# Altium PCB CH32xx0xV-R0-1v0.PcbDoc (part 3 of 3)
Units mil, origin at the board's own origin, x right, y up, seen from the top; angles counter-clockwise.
Board outline 3661.42 x 3267.72 mil, 2 copper layers (Top Layer, Bottom Layer); 68 components, 119 nets, 417 pads, 746 vias.
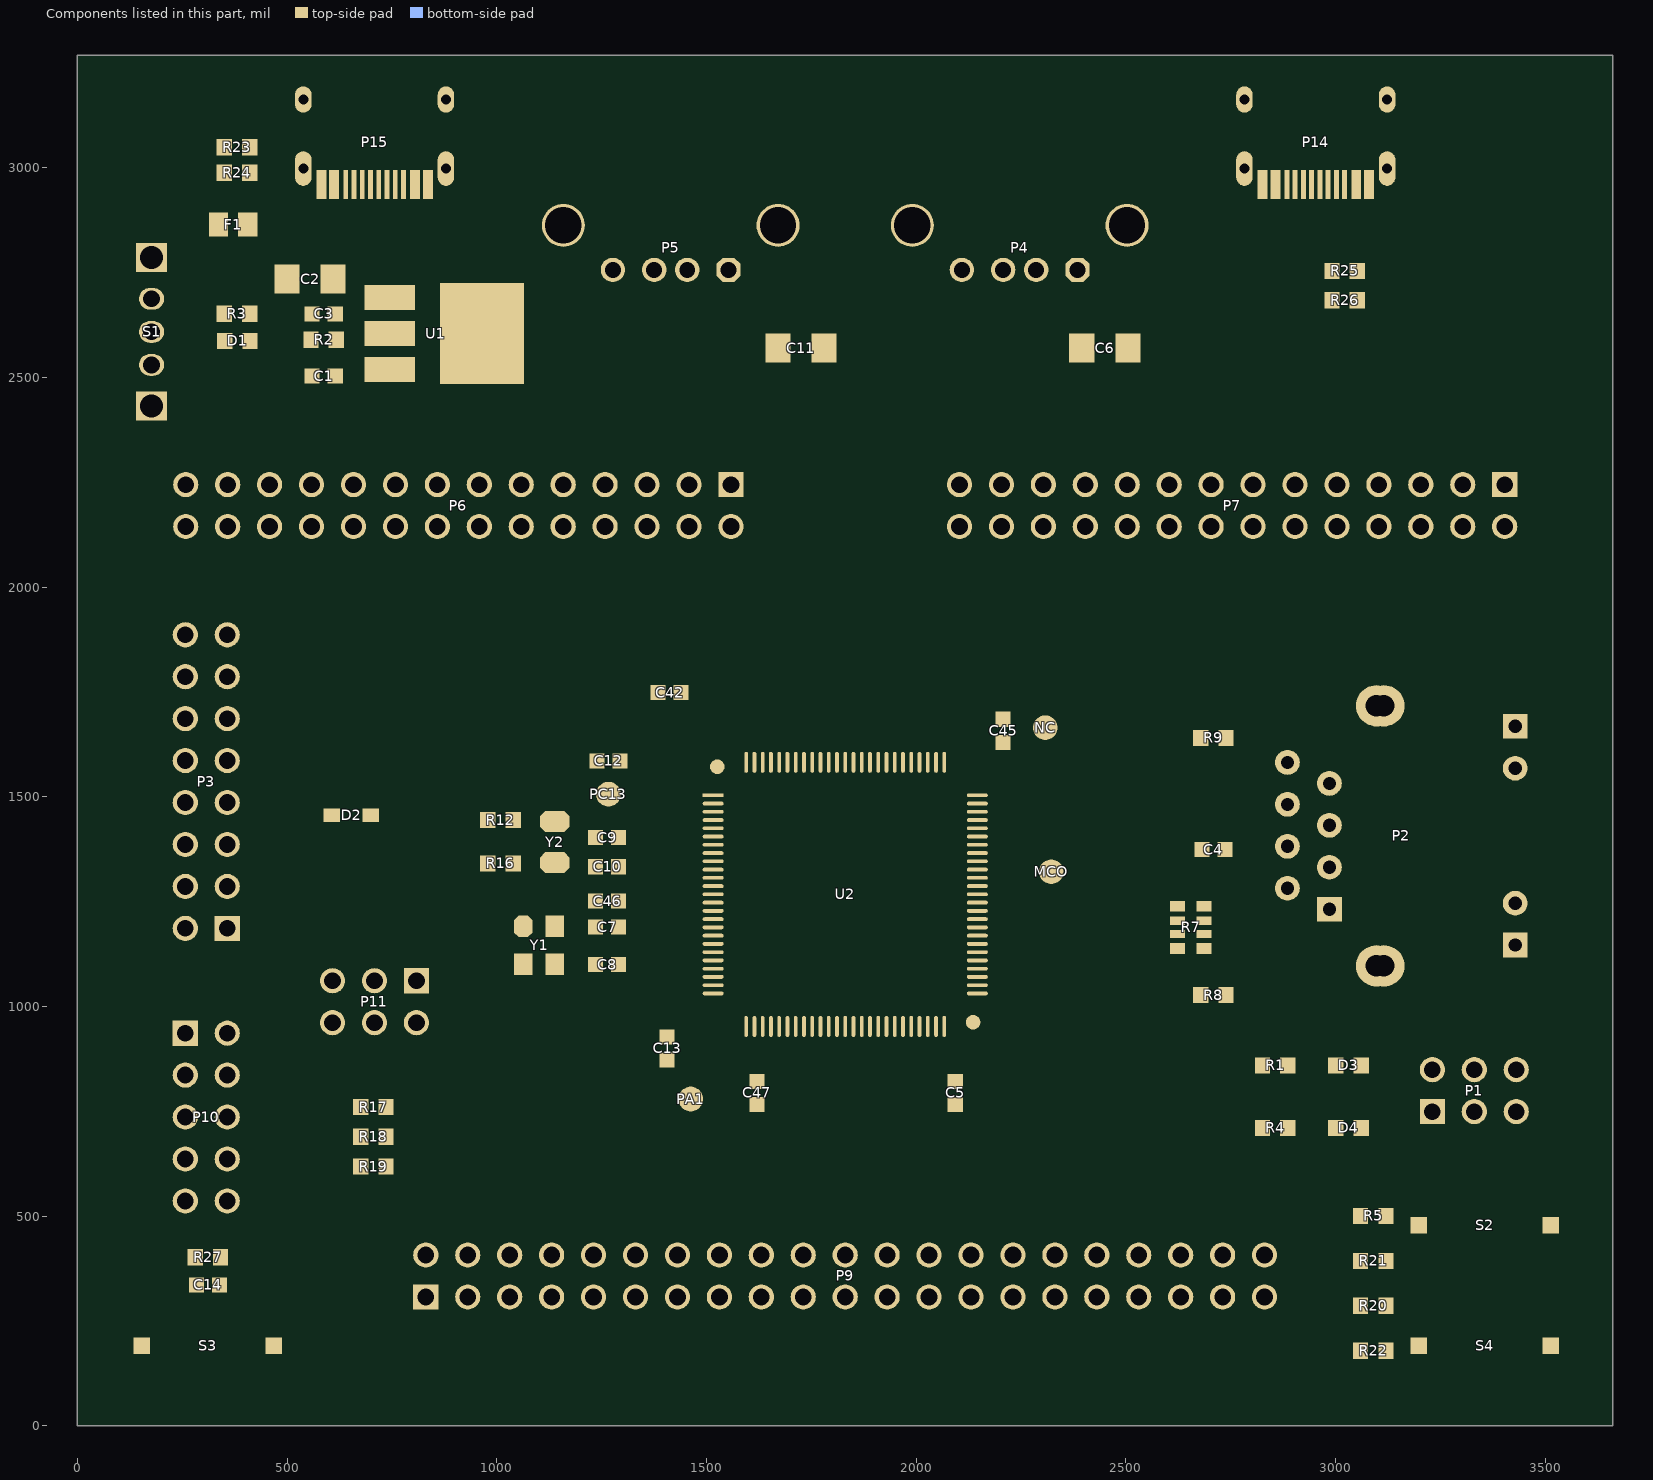
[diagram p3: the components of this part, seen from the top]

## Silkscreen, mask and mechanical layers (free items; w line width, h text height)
Top Overlay:
  lines w10: 471.12,1226.78 471.12,1838.79
  text "OFF" at 24.62,2711.6 h32 r270
  text "ON" at 24.62,2573.76 h32 r270
  text "CH32xx0xV-R0-1v0" at 2720.16,2529.81 h45
  text "PC12" at 2682.57,2465.31 h35 r270
  text "PC10" at 2782.58,2465.31 h35 r270
  text "PA14" at 2882.59,2465.31 h35 r270
  text "PA12" at 2982.6,2465.31 h35 r270
  text "PA10" at 3082.61,2465.31 h35 r270
  text "PC15" at 731.68,2438.82 h35 r270
  text "PC13" at 831.81,2438.82 h35 r270
  text "PB6" at 2082.53,2436.15 h35 r270
  text "PB4" at 2182.54,2436.15 h35 r270
  text "PD7" at 2282.54,2436.15 h35 r270
  text "PD5" at 2382.55,2436.15 h35 r270
  text "PD3" at 2482.56,2436.15 h35 r270
  text "PA8" at 3182.61,2436.15 h35 r270
  text "PC8" at 3282.62,2436.15 h35 r270
  text "PC6" at 3382.63,2436.15 h35 r270
  text "PD1" at 2582.57,2424.49 h35 r270
  text "GND" at 230.13,2409.67 h35 r270
  text "GND" at 330.27,2409.67 h35 r270
  text "PC3" at 531.4,2409.67 h35 r270
  text "PE5" at 931.95,2409.67 h35 r270
  text "PE3" at 1032.09,2409.67 h35 r270
  text "PB9" at 1232.36,2409.67 h35 r270
  text "GND" at 1331.27,2409.67 h35 r270
  text "VIO" at 1431.96,2403.83 h35 r270
  text "VIO" at 1536.38,2403.83 h35 r270
  text "PA1" at 434.68,2398 h35 r270
  text "PC1" at 631.54,2398 h35 r270
  text "PE1" at 1132.22,2398 h35 r270
  text "GND" at 238.88,2082.05 h35 r270
  text "GND" at 339.18,2082.05 h35 r270
  text "PA0" at 435.6,2082.05 h35 r270
  text "PC2" at 540.47,2082.05 h35 r270
  text "PC0" at 640.76,2082.05 h35 r270
  text "PC14" at 741.06,2082.05 h35 r270
  text "PE6" at 841.35,2082.05 h35 r270
  text "PE4" at 941.65,2082.05 h35 r270
  text "PE2" at 1041.94,2082.05 h35 r270
  text "PE0" at 1142.23,2082.05 h35 r270
  text "PB8" at 1242.53,2082.05 h35 r270
  text "PB7" at 1342.82,2082.05 h35 r270
  text "VDD" at 1443.11,2082.05 h35 r270
  text "VDD" at 1543.41,2082.05 h35 r270
  text "GND" at 3186.63,2075.24 h35 r270
  text "PB5" at 2082.53,2072.13 h35 r270
  text "PB3" at 2182.89,2072.13 h35 r270
  text "PD6" at 2283.25,2072.13 h35 r270
  text "PD4" at 2383.61,2072.13 h35 r270
  text "PD2" at 2483.98,2072.13 h35 r270
  text "PD0" at 2584.34,2072.13 h35 r270
  text "PC11" at 2684.7,2072.13 h35 r270
  text "PA15" at 2785.06,2072.13 h35 r270
  text "PA13" at 2885.42,2072.13 h35 r270
  text "PA11" at 2985.79,2072.13 h35 r270
  text "PA9" at 3086.15,2072.13 h35 r270
  text "PC9" at 3285.16,2072.13 h35 r270
  text "PC7" at 3381.51,2072.13 h35 r270
  text "GND" at 423.05,1868.53 h35
  text "3V3" at 77.98,1863.31 h35
  text "3V3" at 77.98,1762.96 h35
  text "3V3" at 77.98,1662.61 h35
  text "5V" at 112.97,1562.26 h35
  text "5V" at 112.97,1461.91 h35
  text "5V" at 112.97,1361.56 h35
  text "GND" at 77.98,1261.21 h35
  text "VBAT" at 683.87,1261.1 h35 r270
  text "VDD" at 583.33,1226.12 h35 r270
  text "VIO" at 788.29,1220.28 h35 r270
  text "GND" at 423.05,1167.39 h35
  text "GND" at 77.98,1160.87 h35
  text "ELED2" at 3409.63,1075.36 h32 r270
  text "ELED1" at 3307.63,1064.69 h32 r270
  text "GND" at 3205.62,1011.38 h32 r270
  text "SWCK" at 39.8,914.85 h35
  text "TXD" at 428.53,912.72 h35
  text "3V3" at 580.11,902.35 h33 r270
  text "3V3" at 687.21,902.35 h33 r270
  text "3V3" at 785.82,902.35 h33 r270
  text "SWIO" at 45.63,814.12 h35
  text "RXD" at 428.53,814.1 h35
  text "GND" at 428.53,714.73 h35
  text "GND" at 74.79,713.39 h35
  text "LED1" at 3205.62,690.33 h32 r270
  text "LED2" at 3307.63,690.33 h32 r270
  text "KEY" at 3409.63,690.33 h32 r270
  text "BOOT1" at 908.09,645.05 h35 r270
  text "PE13" at 1808.96,621.21 h35 r270
  text "PE15" at 1909.06,621.21 h35 r270
  text "PB13" at 2109.25,621.21 h35 r270
  text "PB15" at 2209.35,621.21 h35 r270
  text "PD13" at 2509.64,621.21 h35 r270
  text "PD15" at 2609.73,621.21 h35 r270
  text "VDD" at 428.53,616.11 h35
  text "VDD" at 74.79,612.66 h35
  text "PE11" at 1708.86,609.55 h35 r270
  text "PB11" at 2009.15,609.55 h35 r270
  text "PD11" at 2409.54,609.55 h35 r270
  text "GND" at 807.99,592.05 h35 r270
  text "PA3" at 1008.19,592.05 h35 r270
  text "PA5" at 1108.28,592.05 h35 r270
  text "PA7" at 1208.38,592.05 h35 r270
  text "PC5" at 1308.48,592.05 h35 r270
  text "PE7" at 1508.67,592.05 h35 r270
  text "PE9" at 1608.77,592.05 h35 r270
  text "PD9" at 2309.44,592.05 h35 r270
  text "GND" at 2709.83,592.05 h35 r270
  text "GND" at 2809.93,592.05 h35 r270
  text "PB1" at 1408.57,580.39 h35 r270
  text "5V" at 109.78,511.93 h35
  text "5V" at 428.53,512.3 h35
  text "GND" at 807.99,217.56 h35 r270
  text "BOOT0" at 908.09,217.56 h35 r270
  text "PA2" at 1008.19,217.56 h35 r270
  text "PA4" at 1108.28,217.56 h35 r270
  text "PA6" at 1208.38,217.56 h35 r270
  text "PC4" at 1308.48,217.56 h35 r270
  text "PB0" at 1408.57,217.56 h35 r270
  text "PB2" at 1508.67,217.56 h35 r270
  text "PE8" at 1608.77,217.56 h35 r270
  text "PE10" at 1708.86,217.56 h35 r270
  text "PE12" at 1808.96,217.56 h35 r270
  text "PE14" at 1909.06,217.56 h35 r270
  text "PB10" at 2009.15,217.56 h35 r270
  text "PB12" at 2109.25,217.56 h35 r270
  text "PB14" at 2209.35,217.56 h35 r270
  text "PD8" at 2309.45,217.56 h35 r270
  text "PD10" at 2409.54,217.56 h35 r270
  text "PD12" at 2509.64,217.56 h35 r270
  text "PD14" at 2609.74,217.56 h35 r270
  text "GND" at 2709.83,217.56 h35 r270
  text "GND" at 2809.93,217.56 h35 r270
Mechanical 1:
  the board outline again, w10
